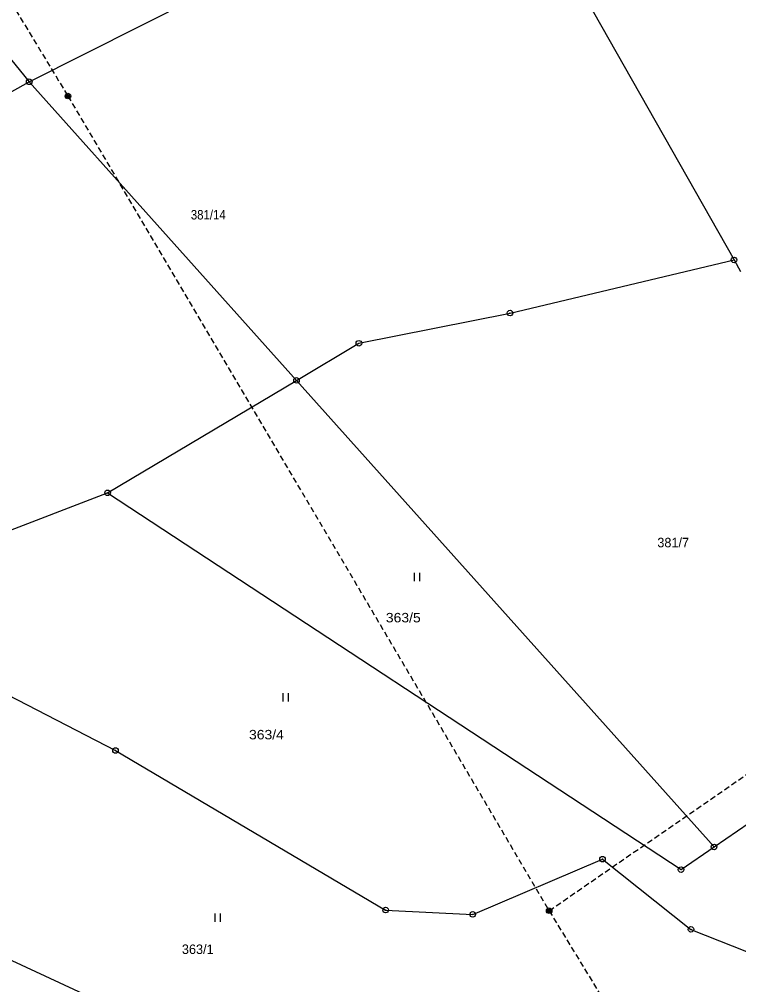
# Model space of a CAD drawing. Extents: x -592965 to -592390, y -1145071 to -1144631.
# Drawn here: x -592769.5 to -592704.9, y -1144880.5 to -1144793.9 of the extents above; entities that cross this region are included whole.
import ezdxf

# ---------------------------------------------------------------- set-up
doc = ezdxf.new("R2010")
doc.units = 0
doc.header["$LTSCALE"] = 0.17
doc.linetypes.add('MEDIUM_DASHED', pattern=[4.5, 3, -1.5])
doc.layers.add('4', color=7, linetype='Continuous', lineweight=25)

msp = doc.modelspace()

# ---------------------------------------------------------------- linework, layer by layer
at = {"layer": '4'}
for p, q in [((-592787.07, -1144776.8), (-592768.57, -1144799.46)), ((-592724.27, -1144782.05), (-592705.33, -1144815.45)), ((-592768.57, -1144799.46), (-592737.33, -1144783.72)), ((-592786.95, -1144809.64), (-592768.57, -1144799.46)), ((-592725.43, -1144820.22), (-592705.33, -1144815.45)), ((-592705.33, -1144815.45), (-592704.74, -1144816.49)), ((-592738.99, -1144822.93), (-592725.43, -1144820.22)), ((-592744.59, -1144826.26), (-592738.99, -1144822.93)), ((-592761.54, -1144836.35), (-592744.59, -1144826.26)), ((-592744.59, -1144826.26), (-592707.12, -1144868.13)), ((-592778.79, -1144842.96), (-592761.54, -1144836.35)), ((-592761.54, -1144836.35), (-592710.08, -1144870.17)), ((-592734.018, -1144843.542), (-592734.018, -1144844.292)), ((-592733.508, -1144844.292), (-592733.508, -1144843.542)), ((-592784.2, -1144847.38), (-592760.83, -1144859.48)), ((-592745.818, -1144854.342), (-592745.818, -1144855.092)), ((-592745.308, -1144855.092), (-592745.308, -1144854.342)), ((-592760.83, -1144859.48), (-592736.59, -1144873.8)), ((-592707.12, -1144868.13), (-592700.32, -1144863.43)), ((-592794.59, -1144867.05), (-592749.94, -1144887.66)), ((-592710.08, -1144870.17), (-592707.12, -1144868.13)), ((-592728.78, -1144874.19), (-592717.13, -1144869.23)), ((-592717.13, -1144869.23), (-592709.19, -1144875.53)), ((-592751.928, -1144874.102), (-592751.928, -1144874.852)), ((-592751.418, -1144874.852), (-592751.418, -1144874.102)), ((-592736.59, -1144873.8), (-592728.78, -1144874.19)), ((-592709.19, -1144875.53), (-592699.12, -1144879.54))]:
    msp.add_line(p, q, dxfattribs=at)
at = {"layer": '4', "lineweight": 13}
msp.add_line((-592768.57, -1144799.46), (-592744.59, -1144826.26), dxfattribs=at)
at = {"layer": '4', "linetype": 'MEDIUM_DASHED'}
for points in [[(-592857.7, -1144647.96), (-592827.25, -1144698.04), (-592798.73, -1144745.3), (-592765.1, -1144800.74), (-592721.92, -1144873.86), (-592693.51, -1144920.47), (-592669.72, -1144961.82), (-592709.34, -1144973.09), (-592761.29, -1144989.89), (-592825.83, -1145034.08), (-592878.88, -1145071.17)], [(-592721.92, -1144873.86), (-592691.99, -1144853.21), (-592654.82, -1144827.23)]]:
    msp.add_lwpolyline(points, dxfattribs=at)
at = {"layer": '4'}
for centre, radius in [((-592768.57, -1144799.46), 0.25), ((-592768.57, -1144799.46), 0.0164), ((-592765.1, -1144800.74), 0.25), ((-592765.1, -1144800.74), 0.15), ((-592765.1, -1144800.74), 0.075), ((-592705.33, -1144815.45), 0.25), ((-592705.33, -1144815.45), 0.0164), ((-592725.43, -1144820.22), 0.25), ((-592725.43, -1144820.22), 0.0164), ((-592738.99, -1144822.93), 0.25), ((-592738.99, -1144822.93), 0.0164), ((-592744.59, -1144826.26), 0.25), ((-592744.59, -1144826.26), 0.0164), ((-592761.54, -1144836.35), 0.25), ((-592761.54, -1144836.35), 0.0164), ((-592760.83, -1144859.48), 0.25), ((-592760.83, -1144859.48), 0.0164), ((-592707.12, -1144868.13), 0.25), ((-592707.12, -1144868.13), 0.0164), ((-592717.13, -1144869.23), 0.25), ((-592717.13, -1144869.23), 0.0164), ((-592710.08, -1144870.17), 0.25), ((-592710.08, -1144870.17), 0.0164), ((-592736.59, -1144873.8), 0.25), ((-592736.59, -1144873.8), 0.0164), ((-592728.78, -1144874.19), 0.25), ((-592728.78, -1144874.19), 0.0164), ((-592721.92, -1144873.86), 0.25), ((-592721.92, -1144873.86), 0.15), ((-592721.92, -1144873.86), 0.075), ((-592709.19, -1144875.53), 0.25), ((-592709.19, -1144875.53), 0.0164)]:
    msp.add_circle(centre, radius, dxfattribs=at)

# ---------------------------------------------------------------- texts
for s, width, p in [('381/14', 0.9, (-592754.07, -1144811.82)), ('363/5', 1.1, (-592736.57, -1144847.98)), ('363/4', 1.1, (-592748.85, -1144858.48))]:
    msp.add_text(s, height=0.85, dxfattribs=dict(at, width=width)).set_placement(p)
for s, p in [('381/7', (-592712.21, -1144841.24)), ('363/1', (-592754.87, -1144877.74))]:
    msp.add_text(s, height=0.85, dxfattribs=at).set_placement(p)

doc.saveas('drawing.dxf')
